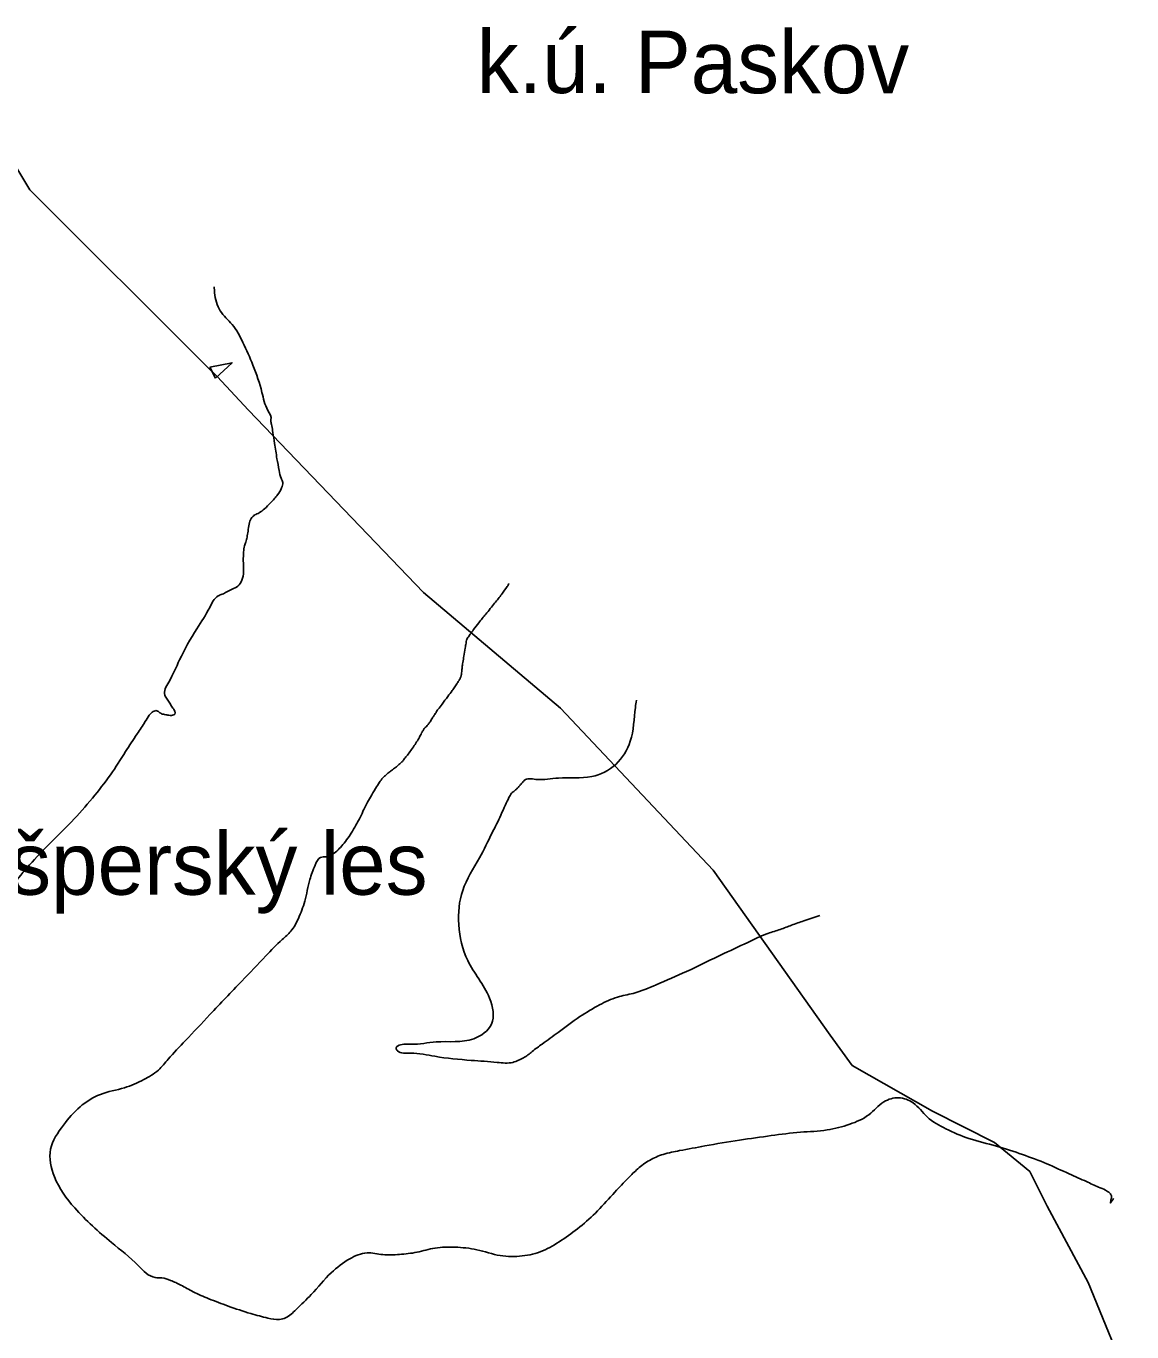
# Model space of a CAD drawing. Extents: x -478645 to -472650, y -1118147 to -1113892.
# Drawn here: x -473519.1 to -473165.6, y -1115290.7 to -1114873.3 of the extents above; entities that cross this region are included whole.
import ezdxf

# ---------------------------------------------------------------- set-up
doc = ezdxf.new("R2010")
doc.units = 0
for name, color, linetype in [('cesty', 7, 'Continuous'), ('místní názvy', 7, 'Continuous'), ('ObPÚ', 7, 'Continuous'), ('okolní k_ú_', 7, 'Continuous'), ('Vrstevnice_vedlejsi', 7, 'Continuous')]:
    doc.layers.add(name, color=color, linetype=linetype)

msp = doc.modelspace()

# ---------------------------------------------------------------- linework, layer by layer
at = {"layer": 'cesty'}
msp.add_line((-473460.394, -1114982.304), (-473458.585, -1114985.872), dxfattribs=at)
msp.add_lwpolyline([(-473458.585, -1114985.872), (-473453.294, -1114980.946), (-473460.394, -1114982.304)], dxfattribs=at)
at = {"layer": 'ObPÚ'}
msp.add_lwpolyline([(-473540.1, -1114888.89), (-473517.91, -1114925.63), (-473460.91, -1114982.6), (-473458.09, -1114985.31), (-473447.97, -1114996.07), (-473392.04, -1115054.42), (-473348.23, -1115091.37), (-473299.48, -1115143.13), (-473262.02, -1115195.86), (-473255.04, -1115205.53), (-473229.36, -1115220.1), (-473209.49, -1115230.13), (-473198.21, -1115239.44), (-473192.61, -1115250.47), (-473179.5, -1115274.93), (-473165.56, -1115309.03)], dxfattribs=at)
at = {"layer": 'Vrstevnice_vedlejsi'}
for points in [[(-473446.07, -1115029.557), (-473444.606, -1115028.916), (-473442.895, -1115027.628), (-473440.937, -1115025.693), (-473438.733, -1115023.112), (-473437.443, -1115020.947), (-473437.068, -1115019.199), (-473437.608, -1115017.868), (-473438.222, -1115015.342), (-473438.91, -1115011.623), (-473439.673, -1115006.71), (-473440.231, -1115003.188), (-473440.584, -1115001.058), (-473440.733, -1115000.318), (-473440.834, -1114999.788), (-473440.887, -1114999.467), (-473440.894, -1114999.355), (-473440.892, -1114999.263), (-473440.883, -1114999.192), (-473440.866, -1114999.14), (-473441.815, -1114996.209), (-473443.731, -1114990.401), (-473446.614, -1114981.714), (-473449.794, -1114974.475), (-473453.272, -1114968.685), (-473457.047, -1114964.342), (-473458.854, -1114958.606), (-473458.98, -1114956.638)], [(-473650.089, -1115300.41), (-473650.269, -1115300.331), (-473651.195, -1115299.885), (-473652.867, -1115299.071), (-473655.284, -1115297.889), (-473656.698, -1115296.836), (-473657.11, -1115295.914), (-473656.519, -1115295.121), (-473655.217, -1115293.422), (-473653.203, -1115290.818), (-473650.478, -1115287.308), (-473648.644, -1115284.706), (-473647.701, -1115283.01), (-473647.649, -1115282.222), (-473647.397, -1115281.539), (-473646.944, -1115280.961), (-473646.29, -1115280.489), (-473645.684, -1115279.766), (-473645.125, -1115278.792), (-473644.613, -1115277.566), (-473643.817, -1115276.531), (-473642.735, -1115275.688), (-473641.367, -1115275.035), (-473636.09, -1115270.78), (-473626.902, -1115262.922), (-473613.803, -1115251.461), (-473605.017, -1115243.633), (-473600.543, -1115239.437), (-473600.38, -1115238.875), (-473600.075, -1115237.644), (-473599.625, -1115235.744), (-473599.032, -1115233.177), (-473598.486, -1115231.282), (-473597.988, -1115230.061), (-473597.536, -1115229.512), (-473597.166, -1115229.118), (-473596.877, -1115228.878), (-473596.67, -1115228.792), (-473595.297, -1115227.077), (-473592.758, -1115223.733), (-473589.054, -1115218.761), (-473585.864, -1115213.914), (-473583.191, -1115209.193), (-473581.033, -1115204.596), (-473578.545, -1115200.484), (-473575.729, -1115196.854), (-473572.583, -1115193.709), (-473569.437, -1115191.312), (-473566.291, -1115189.664), (-473563.146, -1115188.765), (-473557.952, -1115185.07), (-473550.711, -1115178.578), (-473541.422, -1115169.289), (-473533.882, -1115161.209), (-473528.089, -1115154.338), (-473524.045, -1115148.675), (-473518.791, -1115142.343), (-473512.329, -1115135.342), (-473504.658, -1115127.671), (-473497.935, -1115120.094), (-473492.161, -1115112.612), (-473487.335, -1115105.225), (-473483.654, -1115099.59), (-473481.119, -1115095.709), (-473479.73, -1115093.581), (-473478.473, -1115092.391), (-473477.347, -1115092.139), (-473476.354, -1115092.824), (-473475.18, -1115093.297), (-473473.826, -1115093.56), (-473472.291, -1115093.611), (-473471.54, -1115093.208), (-473471.573, -1115092.351), (-473472.39, -1115091.039), (-473473.202, -1115089.739), (-473474.009, -1115088.451), (-473474.812, -1115087.176), (-473473.502, -1115083.004), (-473470.077, -1115075.935), (-473464.538, -1115065.968), (-473460.42, -1115059.142), (-473457.721, -1115055.455), (-473456.442, -1115054.908), (-473454.962, -1115054.204), (-473453.279, -1115053.341), (-473451.393, -1115052.321), (-473450.165, -1115050.453), (-473449.594, -1115047.737), (-473449.68, -1115044.173), (-473449.591, -1115041.403), (-473449.327, -1115039.426), (-473448.889, -1115038.243), (-473448.495, -1115036.692), (-473448.145, -1115034.773), (-473447.839, -1115032.486), (-473447.147, -1115030.747), (-473446.07, -1115029.557)], [(-473386.124, -1115090.037), (-473384.273, -1115087.586), (-473382.903, -1115085.74), (-473382.013, -1115084.499), (-473381.603, -1115083.862), (-473381.248, -1115083.313), (-473380.947, -1115082.854), (-473380.7, -1115082.483), (-473380.524, -1115082.211), (-473380.419, -1115082.037), (-473380.385, -1115081.962), (-473380.362, -1115081.9), (-473380.35, -1115081.851), (-473380.349, -1115081.814), (-473380.331, -1115081.762), (-473380.297, -1115081.694), (-473380.247, -1115081.611), (-473380.188, -1115081.484), (-473380.121, -1115081.314), (-473380.047, -1115081.1), (-473379.953, -1115080.54), (-473379.84, -1115079.635), (-473379.708, -1115078.383), (-473379.483, -1115076.729), (-473379.164, -1115074.672), (-473378.752, -1115072.213), (-473378.462, -1115070.513), (-473378.294, -1115069.572), (-473378.249, -1115069.39), (-473377.863, -1115068.769), (-473377.134, -1115067.709), (-473376.064, -1115066.21), (-473374.403, -1115064.06), (-473372.152, -1115061.26), (-473369.311, -1115057.81), (-473367.017, -1115054.865), (-473365.272, -1115052.423), (-473364.707, -1115051.531)], [(-473323.958, -1115088.792), (-473324.309, -1115091.108), (-473325.948, -1115101.924), (-473330.597, -1115109.292), (-473338.256, -1115113.211), (-473348.924, -1115113.682), (-473356.125, -1115114.095), (-473359.857, -1115114.449), (-473360.121, -1115114.745), (-473360.405, -1115115.067), (-473360.711, -1115115.415), (-473361.037, -1115115.789), (-473361.327, -1115116.125), (-473361.582, -1115116.421), (-473361.8, -1115116.679), (-473362.046, -1115116.933), (-473362.32, -1115117.181), (-473362.621, -1115117.425), (-473362.988, -1115117.735), (-473363.42, -1115118.114), (-473363.917, -1115118.56), (-473364.736, -1115119.945), (-473365.875, -1115122.269), (-473367.336, -1115125.533), (-473370.099, -1115131.176), (-473374.165, -1115139.198), (-473379.533, -1115149.599), (-473380.789, -1115160.533), (-473377.933, -1115172.001), (-473370.965, -1115184.003), (-473370.319, -1115192.337), (-473375.997, -1115197.004), (-473387.999, -1115198.004), (-473396.12, -1115198.782), (-473400.362, -1115199.336), (-473400.724, -1115199.668), (-473400.845, -1115200.037), (-473400.724, -1115200.443), (-473400.362, -1115200.885), (-473396.253, -1115201.61), (-473388.398, -1115202.617), (-473376.797, -1115203.906), (-473368.485, -1115204.549), (-473363.463, -1115204.545), (-473361.732, -1115203.896), (-473360.133, -1115203.102), (-473358.668, -1115202.165), (-473357.336, -1115201.082), (-473354.125, -1115198.683), (-473349.035, -1115194.967), (-473342.067, -1115189.934), (-473335.744, -1115186.177), (-473330.066, -1115183.694), (-473325.033, -1115182.486), (-473317.677, -1115179.76), (-473307.999, -1115175.517), (-473295.997, -1115169.757), (-473287.322, -1115165.703), (-473281.971, -1115163.357), (-473279.947, -1115162.717), (-473278.003, -1115162.06), (-473276.141, -1115161.385), (-473274.36, -1115160.693), (-473270.458, -1115159.326), (-473265.313, -1115157.582)], [(-473321.772, -1115237.121), (-473323.543, -1115238.561), (-473326.574, -1115241.524), (-473330.864, -1115246.012), (-473336.414, -1115252.024), (-473342.118, -1115257.16), (-473347.976, -1115261.418), (-473353.988, -1115264.8), (-473360.501, -1115266.428), (-473367.515, -1115266.303), (-473375.03, -1115264.424), (-473381.98, -1115263.619), (-473388.364, -1115263.888), (-473394.182, -1115265.231), (-473399.747, -1115265.931), (-473405.059, -1115265.99), (-473410.119, -1115265.406), (-473415.617, -1115267.336), (-473421.555, -1115271.779), (-473427.931, -1115278.735), (-473432.815, -1115283.549), (-473436.206, -1115286.219), (-473438.103, -1115286.746), (-473441.792, -1115286.289), (-473447.273, -1115284.848), (-473454.545, -1115282.424), (-473460.701, -1115280.095), (-473465.74, -1115277.861), (-473469.661, -1115275.722), (-473472.989, -1115274.251), (-473475.722, -1115273.449), (-473477.861, -1115273.316), (-473483.22, -1115269.54), (-473491.798, -1115262.121), (-473503.596, -1115251.061), (-473510.093, -1115241.122), (-473511.29, -1115232.306), (-473507.187, -1115224.611), (-473501.886, -1115218.769), (-473495.389, -1115214.78), (-473487.694, -1115212.642), (-473481.514, -1115210.05), (-473476.848, -1115207.003), (-473473.697, -1115203.502), (-473468.202, -1115197.595), (-473460.364, -1115189.282), (-473450.182, -1115178.565), (-473442.474, -1115170.548), (-473437.239, -1115165.231), (-473434.478, -1115162.616), (-473432.085, -1115158.563), (-473430.058, -1115153.073), (-473428.4, -1115146.146), (-473426.705, -1115141.466), (-473424.975, -1115139.033), (-473423.208, -1115138.847), (-473421.492, -1115138.178), (-473419.827, -1115137.026), (-473418.212, -1115135.39), (-473416.654, -1115133.468), (-473415.153, -1115131.259), (-473413.709, -1115128.764), (-473412.563, -1115126.677), (-473411.715, -1115125), (-473411.166, -1115123.731), (-473410.271, -1115121.983), (-473409.028, -1115119.755), (-473407.438, -1115117.049), (-473406.13, -1115115.009), (-473405.102, -1115113.635), (-473404.355, -1115112.927), (-473403.425, -1115112.133), (-473402.311, -1115111.252), (-473401.014, -1115110.285), (-473399.914, -1115109.377), (-473399.013, -1115108.528), (-473398.309, -1115107.738), (-473397.452, -1115106.668), (-473396.441, -1115105.318), (-473395.277, -1115103.688), (-473394.261, -1115102.133), (-473393.393, -1115100.656), (-473392.673, -1115099.254), (-473392.058, -1115098.213), (-473391.548, -1115097.531), (-473391.142, -1115097.208), (-473390.614, -1115096.586), (-473389.965, -1115095.663), (-473389.192, -1115094.44), (-473388.639, -1115093.582), (-473388.304, -1115093.091), (-473388.188, -1115092.965), (-473388.099, -1115092.842), (-473388.039, -1115092.722), (-473388.007, -1115092.605), (-473387.368, -1115091.709), (-473386.124, -1115090.037)], [(-473171.355, -1115248.095), (-473171.981, -1115248.936), (-473172.361, -1115249.443), (-473172.42, -1115249.513), (-473172.391, -1115249.199), (-473172.273, -1115248.501), (-473172.066, -1115247.42), (-473172.655, -1115246.374), (-473174.04, -1115245.364), (-473176.221, -1115244.39), (-473180.075, -1115242.663), (-473185.602, -1115240.183), (-473192.801, -1115236.951), (-473200.544, -1115233.994), (-473208.831, -1115231.311), (-473217.662, -1115228.902), (-473225.051, -1115225.796), (-473230.996, -1115221.991), (-473235.498, -1115217.489), (-473240.115, -1115215.873), (-473244.848, -1115217.143), (-473249.697, -1115221.299), (-473255.758, -1115224.305), (-473263.03, -1115226.162), (-473271.515, -1115226.869), (-473280.848, -1115227.953), (-473291.03, -1115229.414), (-473302.061, -1115231.253), (-473310.182, -1115232.766), (-473315.394, -1115233.955), (-473317.697, -1115234.818), (-473319.823, -1115235.874), (-473321.772, -1115237.121)]]:
    msp.add_spline(points, degree=3, dxfattribs=at)

# ---------------------------------------------------------------- texts
at = {"layer": 'místní názvy'}
msp.add_text('Brušperský les', height=20, rotation=359.99999, dxfattribs=at).set_placement((-473566.149, -1115150.973))
at = {"layer": 'okolní k_ú_'}
msp.add_text('k.ú. Paskov', height=20, rotation=359.96189, dxfattribs=at).set_placement((-473375.017, -1114894.731))

doc.saveas('drawing.dxf')
